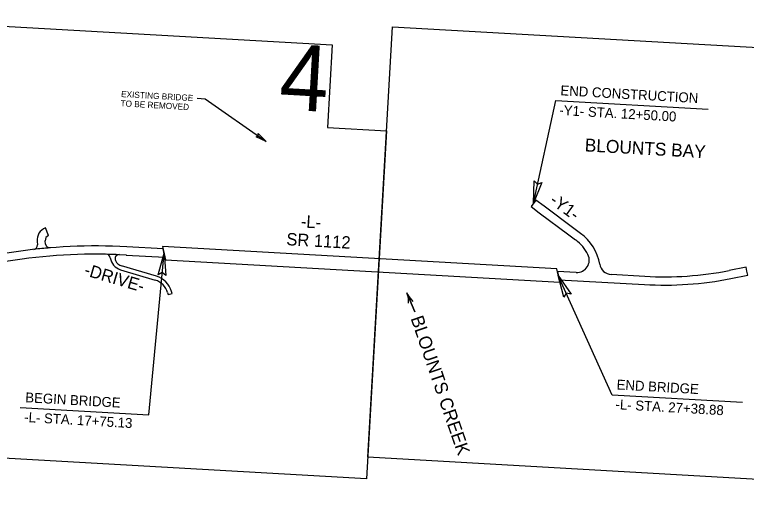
# Model space of a CAD drawing. Extents: x 2601627 to 2606907, y 616646 to 620530.
# Drawn here: x 2603669 to 2605452, y 617939 to 619100 of the extents above; entities that cross this region are included whole.
import ezdxf

# ---------------------------------------------------------------- set-up
doc = ezdxf.new("R2010")
doc.units = 0
for name, color, linetype in [('Default', 7, 'Continuous'), ('Exist Hydro Stream or Body of Water', 7, 'Continuous'), ('Prop DSN Text', 7, 'Continuous'), ('Prop Horizontal Alignment Station Label', 7, 'Continuous'), ('Prop Shade Light', 7, 'Continuous'), ('Prop Terminator CELL', 7, 'Continuous'), ('Sheet Data Field CELL', 7, 'Continuous'), ('Sheet Title CELL', 7, 'Continuous')]:
    doc.layers.add(name, color=color, linetype=linetype)

# ---------------------------------------------------------------- blocks, each defined once
blk = doc.blocks.new('EXIST HYDRO RIVER FLOW ARROW')
at = {"layer": 'Default'}
blk.add_line((0, 0), (0, 0), dxfattribs=at)
blk.add_lwpolyline([(0, 0.04575), (0.03775, 0.03), (0.07725, 0.01725), (0.118, 0.00775), (0.159, 0.0015), (0.2, 0), (-0.2, 0), (0.2, 0), (0.159, -0.0015), (0.118, -0.00775), (0.07725, -0.01725), (0.03775, -0.03), (0, -0.04575)], dxfattribs=at)

msp = doc.modelspace()

# ---------------------------------------------------------------- linework, layer by layer
at = {"layer": 'Prop DSN Text'}
for p, q in [((2604113.4, 618896.3), (2604133.4, 618895.1)), ((2604133.4, 618895.1), (2604282, 618790.7))]:
    msp.add_line(p, q, dxfattribs=at)
at = {"layer": 'Prop Horizontal Alignment Station Label'}
for p, q in [((2604933, 618640.5), (2604987.6, 618890.6)), ((2604987.6, 618890.6), (2605358.8, 618869.5))]:
    msp.add_line(p, q, dxfattribs=at)
for points in [[(2603682.8, 618143), (2603995.7, 618125.1), (2604033, 618519.4)], [(2605442.1, 618155.5), (2605125, 618173.5), (2604993.6, 618464.7)]]:
    msp.add_lwpolyline(points, dxfattribs=at)
at = {"layer": 'Prop Shade Light'}
for p, q in [((2604938.5, 618648), (2604927.4, 618633)), ((2603751.3, 618561.9), (2603744.3, 618580.6)), ((2605019.6, 618563.5), (2605035.9, 618551.3)), ((2603723.7, 618547.5), (2603724.5, 618539.2)), ((2603744.4, 618541.1), (2603743.6, 618549.5)), ((2604031, 618529.5), (2603942.2, 618534.6)), ((2604035.2, 618509.3), (2604031, 618529.5)), ((2603941.1, 618514.6), (2604035.2, 618509.3)), ((2604014.3, 618463), (2603929.7, 618488.3)), ((2603926.8, 618478.7), (2604011.4, 618453.4)), ((2605037.4, 618472.2), (2604991.4, 618474.8)), ((2604991.4, 618474.8), (2604995.6, 618454.5)), ((2605451.4, 618485), (2605410.3, 618476.9)), ((2604995.6, 618454.5), (2605203.3, 618442.7)), ((2605204.5, 618462.7), (2605122.3, 618467.4)), ((2605414.2, 618457.2), (2605455.3, 618465.3)), ((2604041.7, 618423), (2604043.1, 618418.5)), ((2604043.1, 618418.5), (2604052.6, 618421.3)), ((2604052.6, 618421.3), (2604051.3, 618425.8))]:
    msp.add_line(p, q, dxfattribs=at)
for points in [[(2604927.4, 618633), (2604946.9, 618617.3), (2605019.6, 618563.5)], [(2605047.8, 618567.4), (2605031.5, 618579.5), (2604958.8, 618633.4), (2604938.5, 618648)], [(2605455.3, 618465.3), (2605453.3, 618475.1), (2605451.4, 618485)]]:
    msp.add_lwpolyline(points, dxfattribs=at)
msp.add_lwpolyline([(2604029.6, 618535.7), (2604036.3, 618503), (2604997, 618448.3), (2604990.2, 618481)], close=True, dxfattribs=at)
for centre, radius, start, end in [((2603755.5, 618550.7), 32, 110.5387, 185.7636), ((2603755.5, 618550.7), 12, 110.5387, 185.7636), ((2604976.4, 618471), 120, 10.0985, 53.4482), ((2604976.4, 618471), 100, 26.4155, 53.4482), ((2603866.1, 617196.7), 1340, 86.7403, 110.3221), ((2603714.6, 618538.2), 10, 276.4427, 5.7636), ((2603866.1, 617196.7), 1340, 94.745, 96.4427), ((2603754.4, 618542.1), 10, 185.7636, 274.745), ((2603866.1, 617196.7), 1320, 86.7403, 110.3221), ((2603892.2, 618506.5), 10, 7.3649, 88.8558), ((2603866.1, 617196.7), 1320, 87.4887, 88.8558), ((2603936.8, 618512.3), 35, 187.3649, 253.3541), ((2603923.5, 618505.5), 10, 87.4887, 206.8096), ((2605039.1, 618502.2), 30, 266.7403, 26.4155), ((2603936.8, 618512.3), 25, 206.8096, 253.3541), ((2605124, 618497.3), 30, 190.0985, 266.7403), ((2605251.3, 619284.4), 823, 266.7403, 281.1416), ((2603998.6, 618410.3), 45, 16.393, 73.3541), ((2603998.6, 618410.3), 55, 16.393, 73.3541), ((2605251.3, 619284.4), 843, 266.7403, 281.1416)]:
    msp.add_arc(centre, radius, start, end, dxfattribs=at)
at = {"layer": 'Prop Terminator CELL'}
for points in [[(2604262.6, 618810.1), (2604282, 618790.7), (2604257.1, 618802.4), (2604262.6, 618804.4)], [(2604953.6, 618691.2), (2604933, 618640.5), (2604935.2, 618695.6), (2604943.1, 618686.8)], [(2604018.6, 618466.5), (2604033, 618519.4), (2604037.4, 618464.4), (2604028.5, 618472.2)], [(2605007.4, 618411.6), (2604993.6, 618464.7), (2605024.7, 618419.1), (2605013.1, 618421.5)]]:
    msp.add_lwpolyline(points, close=True, dxfattribs=at)
at = {"layer": 'Sheet Title CELL'}
for p, q in [((2603144.9, 619099.9), (2604442.8, 619026)), ((2604529.6, 618022), (2604589.3, 619070.3)), ((2604589.3, 619070.3), (2605849.4, 618998.6)), ((2604526.6, 617969.5), (2603085.2, 618051.6)), ((2605984.9, 617939.2), (2604529.6, 618022))]:
    msp.add_line(p, q, dxfattribs=at)
for points in [[(2604442.8, 619026), (2604431.3, 618825.2), (2604431.3, 618825.2)], [(2604431.3, 618825.2), (2604574.9, 618817.1), (2604526.6, 617969.5), (2604526.6, 617969.5)]]:
    msp.add_lwpolyline(points, dxfattribs=at)

# ---------------------------------------------------------------- block references
at = {"layer": 'Exist Hydro Stream or Body of Water', "xscale": 125.00000000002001, "yscale": 125.0000000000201, "rotation": 112.54439797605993}
msp.add_blockref('EXIST HYDRO RIVER FLOW ARROW', (2604634.1, 618399.6), dxfattribs=at)

# ---------------------------------------------------------------- texts
at = {"layer": 'Exist Hydro Stream or Body of Water'}
for s, rotation, p in [('BLOUNTS BAY', 356.7403, (2605057.5, 618767.1)), ('BLOUNTS CREEK', 289.0664, (2604633.4, 618360.5))]:
    msp.add_text(s, height=31.5, rotation=rotation, dxfattribs=at).set_placement(p)
at = {"layer": 'Prop DSN Text'}
for s, p in [('EXISTING BRIDGE', (2603928, 618899.3)), ('TO BE REMOVED', (2603926.7, 618876.8))]:
    msp.add_text(s, height=15, rotation=356.7403, dxfattribs=at).set_placement(p)
at = {"layer": 'Prop Horizontal Alignment Station Label'}
for s, height, rotation, p in [('END CONSTRUCTION', 24.073, 356.7398, (2604998.3, 618903.7)), ('-Y1- STA. 12+50.00', 24.073, 356.7398, (2604995.6, 618855.7)), ('-Y1-', 30.09, 323.8215, (2604970.4, 618642.3)), ('-L-', 30.09, 356.7398, (2604365.6, 618581.9)), ('SR 1112', 30.09, 356.7398, (2604330.4, 618538.7)), ('-DRIVE-', 30.09, 343.4925, (2603836.4, 618466)), ('END BRIDGE', 24.07, 356.7398, (2605135.2, 618187.4)), ('BEGIN BRIDGE', 24.073, 356.7398, (2603694.4, 618156.2)), ('-L- STA. 27+38.88', 24.073, 356.7398, (2605132.5, 618139.4)), ('-L- STA. 17+75.13', 24.073, 356.7398, (2603691.7, 618108.2))]:
    msp.add_text(s, height=height, rotation=rotation, dxfattribs=at).set_placement(p)
at = {"layer": 'Sheet Data Field CELL'}
msp.add_text('4', height=160.4, rotation=356.7398, dxfattribs=at).set_placement((2604311.2, 618869.6))

doc.saveas('drawing.dxf')
